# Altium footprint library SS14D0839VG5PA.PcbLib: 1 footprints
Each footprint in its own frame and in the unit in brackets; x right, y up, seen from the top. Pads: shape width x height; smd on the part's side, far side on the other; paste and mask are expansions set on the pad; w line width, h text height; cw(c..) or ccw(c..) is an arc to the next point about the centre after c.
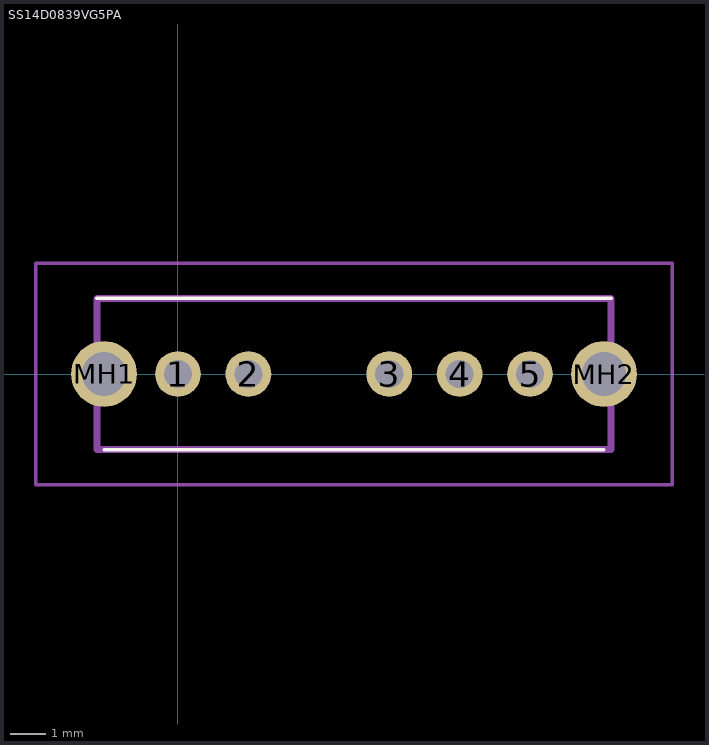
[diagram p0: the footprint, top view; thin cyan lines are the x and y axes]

## SS14D0839VG5PA [mm]
pads (7):
  round 1.3 hole 0.8: 1(0,0) 2(2,0) 3(6,0) 4(8,0) 5(10,0)
  round 1.875 hole 1.25: MH1(-2.1,0) MH2(12.1,0)
Top Overlay:
  lines w0.1: -2.3,2.15 12.3,2.15 ; -2.1,-2.15 12.1,-2.15
Mechanical 15:
  lines w0.2: -2.3,-2.15 12.3,-2.15 12.3,2.15 -2.3,2.15 -2.3,-2.15
Mechanical 20:
  lines w0.1: -4.037,-3.15 14.037,-3.15 14.037,3.15 -4.037,3.15 -4.037,-3.15
3D body "SS14D0839VG5PA.stp": height 5.8, standoff -4.65, extent -10,-3.376 10,3.376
